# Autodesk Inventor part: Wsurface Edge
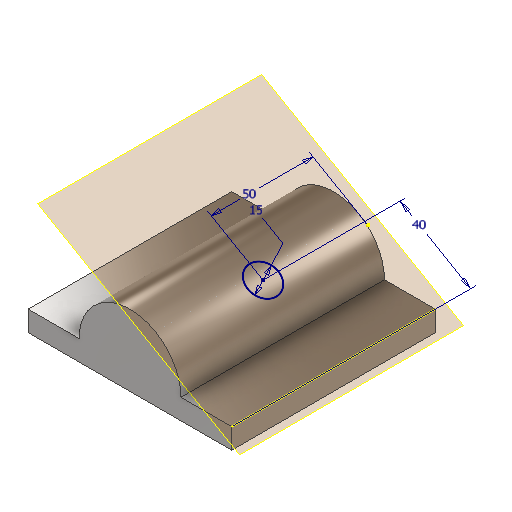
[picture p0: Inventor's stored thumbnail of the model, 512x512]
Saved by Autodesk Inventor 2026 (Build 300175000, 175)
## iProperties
Created: 2022-01
Part Number: Wsurface Edge
Material: Steel, Mild
Document SubType Name: Modeling
Designer: Lars Bertram Pedersen
Density: 7.85 g/cm^3
Appearance: Semi-Polished
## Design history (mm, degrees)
sketch "Sketch1"
  geometry: L1 (-50, 0)-(50, 0); L2 (-50, 0)-(-50, 10); L3 (-50, 10)-(-25, 10); L4 (25, 10)-(50, 10); L5 (50, 10)-(50, 0); A1 r 25 centre (0, 10) between (25, 10) and (-25, 10); 2 further points
  constraints: 10 end point, 3 point on line, 2 perpendicular, 2 point on circle, 1 centre point, 1 coincident, 1 horizontal, 1 midpoint, 1 vertical, 1 vertical alignment
  dimensions: "d0" = 100 distance of L1.start L1.end; "d1" = 25 radius of A1; "d2" = 10 distance of L4.end L1.end
extrude "Extrusion1" new body sketch "Sketch1" distance "d3" = 100; taper "d4" = 0 deg
workplane "Work Plane1"
body "Solid1"
sketch "Sketch2"
  geometry: L1 (0, 0)-(0, 100) reference; C1 r 7.5 at (40, 50); 1 further point
  constraints: 1 centre point
  dimensions: "d5" = 40 distance from line of L1 C1.centre; "d6" = 15 diameter of C1; "d7" = 50 vertical distance of C1.centre point (38.301, 0)
